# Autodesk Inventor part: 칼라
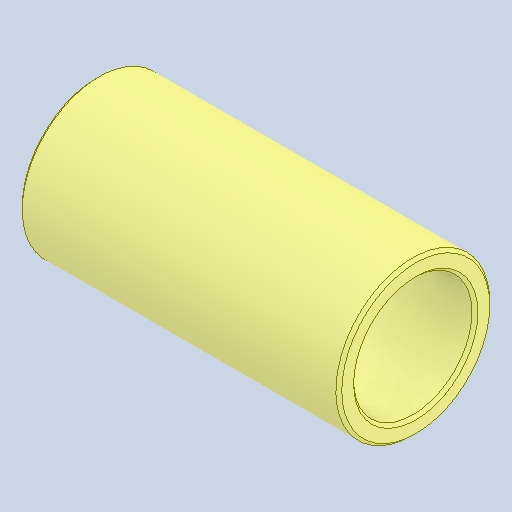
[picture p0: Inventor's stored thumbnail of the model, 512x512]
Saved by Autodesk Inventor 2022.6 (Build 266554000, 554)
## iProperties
Created: 2024-09
Part Number: 칼라
Material: 강철, 연강
Document SubType Name: Modeling
Designer: Class 001
Density: 7.85 g/cm^3
Appearance: 기본값
Author: jhkim
Sending System: Autodesk Inventor 2025
Preprocessor: ST-DEVELOPER v20
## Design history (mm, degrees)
feature "솔리드1"
node "솔리드2"
